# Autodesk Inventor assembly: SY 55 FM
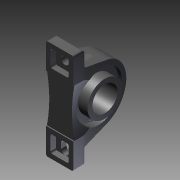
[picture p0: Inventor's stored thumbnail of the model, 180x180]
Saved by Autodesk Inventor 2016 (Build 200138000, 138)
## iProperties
Category: PARTsolutions
Company: SKF
Created: 2016-10
Part Number: SY 55 FM
Catalog Web Link: www.cadenas.de
Description: SY..FM, cast housing, eccentric locking collar-Y-bearing plummer block units
Vendor: SKF
Document SubType Name: Assembly
Designer: psAdmin
Manufacturer: SKF
PSOL_IDENT_0: {$CADENAS_DATA\23d-libs\skf\skf_ps\bearing_units\yunit_syec\yunit_syec_6_1_2_asmtab.prj},221 {VTYP=3
PSOL_IDENT_1: D},{STYP=ASSTAB},{NB=SY 55 FM},{LINA=SY 55 FM},{NN=SY..FM, cast housing, eccentric locking collar},{
PSOL_IDENT_2: DATE=12.09.2016 08:57:23},{GEOMDATE=04.06.2014 11:41:24},{VERSION=},{LINEID=110},{LINESUBID=-1},{WBV
PSOL_IDENT_3: AR=ENDCOVER}  {NB=SY 55 FM},{LINA=SY 55 FM},{KT=DUMMY},{PRODUCTID=211104055},{DESIGNATION=SY 55 FM},
PSOL_IDENT_4: {DESIGNATION2=SY 55 FM},{ENDCOVER=},{PNNB=211104055},{ENDCOVERALG='', 'w/o End Cover', '210000211', '
PSOL_IDENT_5: ECY 211'},{D=55.000},{A=60.000},{H=126.000},{H1=63.500},{L=219.000},{I=25.000},{J=-10000000150474662
PSOL_IDENT_6: 19876688855040.000},{K=-1000000015047466219876688855040.000},{LX=-1000000015047466219876688855040.00
PSOL_IDENT_7: 0},{M=-1000000015047466219876688855040.000},{N=-1000000015047466219876688855040.000},{O=-10000000150
PSOL_IDENT_8: 47466219876688855040.000},{P=-1000000015047466219876688855040.000},{Q=-10000000150474662198766888550
PSOL_IDENT_9: 40.000},{R=-1000000015047466219876688855040.000},{S=-1000000015047466219876688855040.000},{T=-100000
PSOL_IDENT_10: 0015047466219876688855040.000},{U=-1000000015047466219876688855040.000},{V=-100000001504746621987668
PSOL_IDENT_11: 8855040.000},{W=-1000000015047466219876688855040.000},{X=-1000000015047466219876688855040.000},{Y=-1
PSOL_IDENT_12: 000000015047466219876688855040.000},{Z=-1000000015047466219876688855040.000},{AA=-100000001504746621
PSOL_IDENT_13: 9876688855040.000},{AB=-1000000015047466219876688855040.000},{AC=-1000000015047466219876688855040.00
PSOL_IDENT_14: 0},{AD=-1000000015047466219876688855040.000},{AE=-1000000015047466219876688855040.000},{AF=-10000000
PSOL_IDENT_15: 15047466219876688855040.000},{AG=-1000000015047466219876688855040.000},{LOAD1=43.600},{LOAD2=29.000}
PSOL_IDENT_16: ,{AJ=3600.000},{AK=-1000000015047466219876688855040.000},{AL=-1000000015047466219876688855040.000},{
PSOL_IDENT_17: AM=-1000000015047466219876688855040.000},{AN=-1000000015047466219876688855040.000},{AO=-100000001504
PSOL_IDENT_18: 7466219876688855040.000},{SPEED=3600.000},{AQ=-1000000015047466219876688855040.000},{AR=-10000000150
PSOL_IDENT_19: 47466219876688855040.000},{AS=-1000000015047466219876688855040.000},{AT=-100000001504746621987668885
PSOL_IDENT_20: 5040.000},{AU=-1000000015047466219876688855040.000},{AV=-1000000015047466219876688855040.000},{AW=-1
PSOL_IDENT_21: 000000015047466219876688855040.000},{AX=-1000000015047466219876688855040.000},{AY=-10000000150474662
PSOL_IDENT_22: 19876688855040.000},{AZ=-1000000015047466219876688855040.000},{BA=-1000000015047466219876688855040.0
PSOL_IDENT_23: 00},{BB=-1000000015047466219876688855040.000},{BC=-1000000015047466219876688855040.000},{BD=-1000000
PSOL_IDENT_24: 015047466219876688855040.000},{BE=36.400},{MASS=3.650},{BG=-1000000015047466219876688855040.000},{BH=
PSOL_IDENT_25: -1000000015047466219876688855040.000},{BI=-1000000015047466219876688855040.000},{BJ=-100000001504746
PSOL_IDENT_26: 6219876688855040.000},{BK=-1000000015047466219876688855040.000},{BL=-1000000015047466219876688855040
PSOL_IDENT_27: .000},{BM=-1000000015047466219876688855040.000},{BN=-1000000015047466219876688855040.000},{BO=-10000
PSOL_IDENT_28: 00015047466219876688855040.000},{BP=-1000000015047466219876688855040.000},{BQ=-100000001504746621987
PSOL_IDENT_29: 6688855040.000},{BR=-1000000015047466219876688855040.000},{BS=-1000000015047466219876688855040.000},
PSOL_IDENT_30: {BT=-1000000015047466219876688855040.000},{BU=-1000000015047466219876688855040.000},{BV=-10000000150
PSOL_IDENT_31: 47466219876688855040.000},{BW=-1000000015047466219876688855040.000},{BX=-100000001504746621987668885
PSOL_IDENT_32: 5040.000},{BY=-1000000015047466219876688855040.000},{BZ=-1000000015047466219876688855040.000},{CA=-1
PSOL_IDENT_33: 000000015047466219876688855040.000},{CB=-1000000015047466219876688855040.000},{CC=-10000000150474662
PSOL_IDENT_34: 19876688855040.000},{CD=-1000000015047466219876688855040.000},{CE=-1000000015047466219876688855040.0
PSOL_IDENT_35: 00},{CF=-1000000015047466219876688855040.000},{CG=-1000000015047466219876688855040.000},{CH=-1000000
PSOL_IDENT_36: 015047466219876688855040.000},{CI=-1000000015047466219876688855040.000},{CJ=-10000000150474662198766
PSOL_IDENT_37: 88855040.000},{CK=-1000000015047466219876688855040.000},{CL=-1000000015047466219876688855040.000},{C
PSOL_IDENT_38: M=-1000000015047466219876688855040.000},{CN=-1000000015047466219876688855040.000},{CO=-1000000015047
PSOL_IDENT_39: 466219876688855040.000},{CP=-1000000015047466219876688855040.000},{CQ=-10000000150474662198766888550
PSOL_IDENT_40: 40.000},{CR=-1000000015047466219876688855040.000},{HOUSING=SY 511 M},{CT=211100511},{CU=ECY 211},{CV=
PSOL_IDENT_41: 210000211},{BEARING1=YET 211},{CX=103011211},{CY=-1000000015047466219876688855040.000},{CZ=-10000000
PSOL_IDENT_42: 15047466219876688855040.000},{DA=-1000000015047466219876688855040.000},{DB=-100000001504746621987668
PSOL_IDENT_43: 8855040.000},{DC=-1000000015047466219876688855040.000},{DD=-1000000015047466219876688855040.000},{DE=
PSOL_IDENT_44: -1000000015047466219876688855040.000},{DF=-1000000015047466219876688855040.000},{DG=-100000001504746
PSOL_IDENT_45: 6219876688855040.000},{DH=-1000000015047466219876688855040.000},{TYPEID=211104},{INFO=LINK},{ENDCOVE
PSOL_IDENT_46: RALG2=1},{ENDCOVER3=0},{BEARING=2},{PPATH=yunit_syec_asmtpl.prj},{TAXONOMY=2}
NN: SY..FM, cast housing, eccentric locking collar
NT: Y-bearing plummer block units
NB: SY 55 FM
NBSYN: $DESIGNATION2.
LINA: SY 55 FM
PRODUCTID: 211104055
DESIGNATION: SY 55 FM
DESIGNATION2: SY 55 FM
ENDCOVER: w/o End Cover
D: 55.000
A: 60.000
H: 126.000
H1: 63.500
L: 219.000
LOAD1: 43.600
LOAD2: 29.000
SPEED: 3600.000
MASS: 3.650
HOUSING: SY 511 M
BEARING1: YET 211
INFO: LINK
SUPPLIER: SKF
ARTICLENO: SY 55 FM
BOMINFO: SY 55 FM
CREATOR: CADENAS GmbH
Title: SY 55 FM
Author: Cadenas PARTsolutions
Comments: Y-bearing plummer block units
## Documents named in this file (3)
- C:\Users\ingenieria\Desktop\INGENIERIA\Proyectos\2016\Enfriador_4\Planos\SY 55 FM.iam
- C:\Users\ingenieria\Desktop\INGENIERIA\Proyectos\2016\Enfriador_4\Planos\SY 511 M_25.ipt
- C:\Users\ingenieria\Desktop\INGENIERIA\Proyectos\2016\Enfriador_4\Planos\YET 211 .ipt
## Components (2 placed, 2 different names)
1. SY 511 M_25:1
2. YET 211 :1
